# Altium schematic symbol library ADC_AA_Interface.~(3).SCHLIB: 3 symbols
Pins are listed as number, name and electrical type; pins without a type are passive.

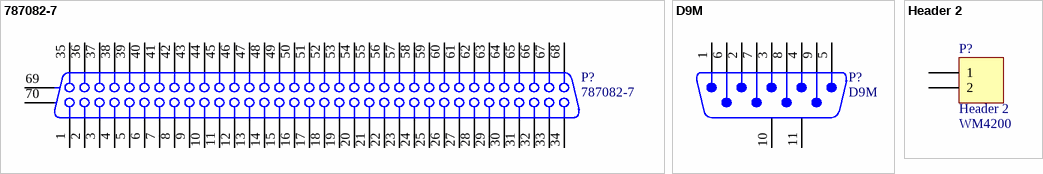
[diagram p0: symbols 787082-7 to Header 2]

## 787082-7
designator P?
Receptacle Assembly, Shielded, Right Angle, AMPLIMITE; Positions: 68; Note: Series III; Gender: Receptacle Header; Note: With Mating Lock; PCB_Layout: Complies with manufacturer's recommendation.; DrillSize: Corresponds to nominal value.
footprint 787082-7 (Connector; D Subminiature 050 Series; 68 Position; Right Angle)
signal-integrity model D Subminiature
pins: 1, 2, 3, 4, 5, 6, 7, 8, 9, 10, 11, 12, 13, 14, 15, 16, 17, 18, 19, 20, 21, 22, 23, 24, 25, 26, 27, 28, 29, 30, 31, 32, 33, 34, 35, 36, 37, 38, 39, 40, 41, 42, 43, 44, 45, 46, 47, 48, 49, 50, 51, 52, 53, 54, 55, 56, 57, 58, 59, 60, 61, 62, 63, 64, 65, 66, 67, 68, 69 MH1, 70 MH2

## D9M
designator P?
9 Position D-Sub Plug, Male Pins Connector; Manufacturer: TE Connectivity; Manufacturer Part Number: 5747871-8; Description: CONN D-SUB PLUG 9POS VERT SOLDER; Plating: Tin; Body Material: Steel; Voltage Rating: 125V; Current Rating: 6A; Max Voltage Rating (DC): 250.25kV; Number of Positions: 9; Number of Ports: 1; Max Supply Voltage (AC): 250V; Mating Connector Lock: Yes (With); PCB Mount Retention: With; PCB Mounting Orientation: Vertical; Preloaded: Yes; Sealable: No (Without); Pitch: 0.108inch; PCB Thickness: 2.36mm; Contact Post Length: 0.125inch; Hole Diameter: 0.12inch; Approvals: UL
signal-integrity model D Subminiature
footprint DB9/M
pins: 1, 2, 3, 4, 5, 6, 7, 8, 9, 10 MH1, 11 MH2

## Header 2
designator P?  Part Number: WM4200
Header, 2-Pin
footprint HDR1X2 (Connector; Header; 2 Position)
signal-integrity model Connector
pins: 1, 2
